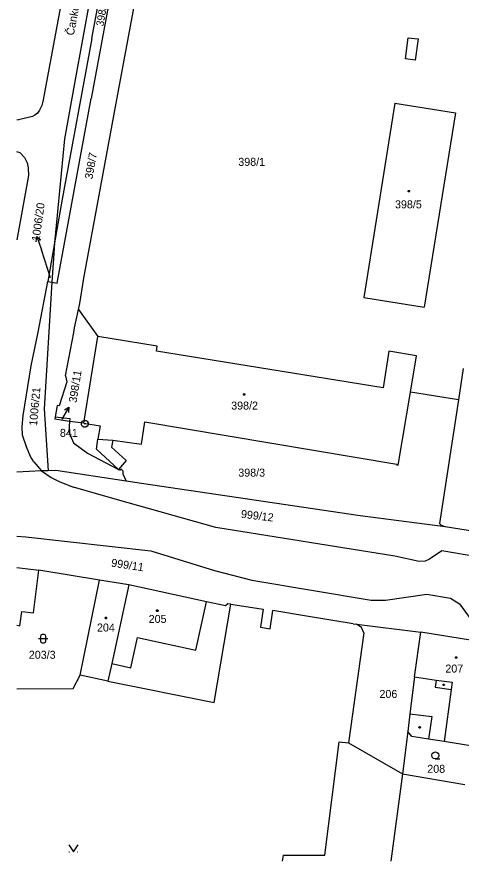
# Model space of a CAD drawing. Extents: x -851495 to -851222, y -1010479 to -1010202.
# Drawn here: x -851494.8 to -851400.4, y -1010478.7 to -1010299.4 of the extents above; entities that cross this region are included whole.
import ezdxf

# ---------------------------------------------------------------- set-up
doc = ezdxf.new("R2010")
doc.units = 0
for name, color, linetype in [('1', 7, 'Continuous'), ('12', 7, 'Continuous'), ('2', 7, 'Continuous'), ('3', 7, 'Continuous'), ('4', 7, 'Continuous'), ('5', 7, 'Continuous'), ('7', 7, 'Continuous'), ('8', 7, 'Continuous')]:
    doc.layers.add(name, color=color, linetype=linetype)

# ---------------------------------------------------------------- blocks, each defined once
blk = doc.blocks.new('101')
blk.add_line((-0.05, 0), (0.05, 0))
blk.add_lwpolyline([(0.19, 0.72), (0.53, 0.53), (0.72, 0.19), (0.72, -0.2), (0.53, -0.54), (0.19, -0.73), (-0.2, -0.73), (-0.54, -0.54), (-0.73, -0.2), (-0.73, 0.19), (-0.54, 0.53), (-0.2, 0.72), (0.19, 0.72)])
blk = doc.blocks.new('304')
blk.add_lwpolyline([(0, 0), (-0.38, 0.1), (-0.65, 0.37), (-0.75, 0.74), (-0.65, 1.11), (-0.38, 1.38), (-0.01, 1.48), (0.36, 1.38), (0.63, 1.11), (0.73, 0.73), (0.63, 0.35), (0.36, 0.08), (-0.02, -0.02), (0.98, -0.02)])
blk = doc.blocks.new('314')
for p, q in [((-0.95, 0), (-0.85, 0)), ((0.85, 0), (0.95, 0))]:
    blk.add_line(p, q)
blk.add_lwpolyline([(-1, 1.5), (0, 0), (1, 1.5)])
blk = doc.blocks.new('316')
for points in [[(-0.5, 1.5), (-0.4, 1.79), (-0.15, 1.97), (0.16, 1.97), (0.41, 1.79), (0.51, 1.5), (0.51, 0.5), (0.41, 0.21), (0.16, 0.03), (-0.15, 0.03), (-0.4, 0.21), (-0.5, 0.5), (-0.5, 1.5)], [(-1, 1), (0.27, 1), (1, 1)]]:
    blk.add_lwpolyline(points)
blk = doc.blocks.new('10292')
blk.add_line((0, 3), (0, 0))
blk.add_lwpolyline([(-0.5, 2), (0, 3), (0.5, 2)])
blk = doc.blocks.new('402')
blk.add_lwpolyline([(0.09, 0.15), (0.18, 0), (0.09, -0.15), (-0.09, -0.15), (-0.18, 0), (-0.09, 0.15), (0.09, 0.15)])
blk = doc.blocks.new('404')
blk.add_lwpolyline([(0, 0.17), (0.1, 0.15), (0.15, 0.06), (0.17, 0), (0.15, -0.09), (0.07, -0.16), (0, -0.17), (-0.09, -0.14), (-0.15, -0.08), (-0.17, 0), (-0.15, 0.09), (-0.07, 0.16), (0, 0.17)])

msp = doc.modelspace()

# ---------------------------------------------------------------- linework, layer by layer
at = {"layer": '1'}
for p, q in [((-851476.12, -1010278.09), (-851482.49, -1010313.06)), ((-851472.11, -1010279.3), (-851479.01, -1010316.73)), ((-851478.85, -1010303.92), (-851474.1, -1010278.46)), ((-851473.7, -1010317.66), (-851466.71, -1010279.81)), ((-851478.85, -1010303.92), (-851485.17, -1010338.09)), ((-851482.49, -1010313.06), (-851484.69, -1010325.27)), ((-851486.26, -1010355.89), (-851479.01, -1010316.73)), ((-851480.57, -1010354.84), (-851473.7, -1010317.66)), ((-851414.5, -1010317.69), (-851421.05, -1010358.97)), ((-851414.5, -1010317.69), (-851401.62, -1010319.76)), ((-851401.62, -1010319.76), (-851408.24, -1010361.02)), ((-851484.69, -1010325.27), (-851486.78, -1010347.37)), ((-851485.17, -1010338.09), (-851486.78, -1010347.37)), ((-851486.78, -1010347.37), (-851488.2, -1010355.55)), ((-851486.78, -1010347.37), (-851486.99, -1010349.59)), ((-851486.99, -1010349.59), (-851487.37, -1010355.7)), ((-851481.45, -1010360.24), (-851480.57, -1010354.84)), ((-851490.26, -1010366.32), (-851488.2, -1010355.55)), ((-851487.37, -1010355.7), (-851489.04, -1010382.57)), ((-851488.2, -1010355.55), (-851487.37, -1010355.7)), ((-851487.37, -1010355.7), (-851486.26, -1010355.89)), ((-851481.71, -1010361.49), (-851481.45, -1010360.24)), ((-851421.05, -1010358.97), (-851408.24, -1010361.02)), ((-851482.53, -1010365.43), (-851481.71, -1010361.49)), ((-851481.71, -1010361.49), (-851477.61, -1010367.22)), ((-851482.71, -1010366.38), (-851482.53, -1010365.43)), ((-851491.75, -1010373.45), (-851490.26, -1010366.32)), ((-851484.5, -1010375.57), (-851482.71, -1010366.38)), ((-851480.57, -1010385.67), (-851477.61, -1010367.22)), ((-851464.98, -1010369.26), (-851477.61, -1010367.22)), ((-851465.15, -1010370.35), (-851464.98, -1010369.26)), ((-851417.01, -1010378.12), (-851465.15, -1010370.35)), ((-851415.76, -1010370.37), (-851417.01, -1010378.12)), ((-851409.91, -1010371.33), (-851415.76, -1010370.37)), ((-851411.16, -1010379.06), (-851409.91, -1010371.33)), ((-851493.5, -1010383.99), (-851491.75, -1010373.45)), ((-851399.98, -1010374.03), (-851401, -1010380.7)), ((-851484.5, -1010375.57), (-851484.17, -1010376.85)), ((-851484.17, -1010376.85), (-851485.79, -1010381.99)), ((-851413.76, -1010394.54), (-851411.16, -1010379.06)), ((-851401, -1010380.7), (-851411.16, -1010379.06)), ((-851486.27, -1010381.9), (-851486.66, -1010384.3)), ((-851485.79, -1010381.99), (-851486.27, -1010381.9)), ((-851401, -1010380.7), (-851405.04, -1010406.96)), ((-851489.04, -1010382.57), (-851488.17, -1010395.75)), ((-851493.7, -1010386.4), (-851493.5, -1010383.99)), ((-851486.66, -1010384.3), (-851486.77, -1010384.83)), ((-851483.62, -1010385.26), (-851486.77, -1010384.83)), ((-851486.66, -1010384.3), (-851483.57, -1010384.66)), ((-851483.62, -1010385.26), (-851483.8, -1010387.52)), ((-851483.57, -1010384.66), (-851483.62, -1010385.26)), ((-851480.57, -1010385.67), (-851477.13, -1010386.23)), ((-851468.32, -1010390.14), (-851467.64, -1010385.34)), ((-851467.64, -1010385.34), (-851414.1, -1010394.33)), ((-851493.63, -1010388.21), (-851493.7, -1010386.4)), ((-851477.13, -1010386.23), (-851477.59, -1010389.03)), ((-851492.79, -1010390.64), (-851493.63, -1010388.21)), ((-851483.8, -1010387.52), (-851482.79, -1010389.85)), ((-851477.59, -1010389.03), (-851474.42, -1010389.28)), ((-851474.42, -1010389.28), (-851468.32, -1010390.14)), ((-851491.92, -1010392.7), (-851492.79, -1010390.64)), ((-851482.79, -1010389.85), (-851479.83, -1010392.05)), ((-851491.22, -1010393.86), (-851491.92, -1010392.7)), ((-851479.83, -1010392.05), (-851473.25, -1010395.45)), ((-851491.22, -1010393.86), (-851489.57, -1010395.79)), ((-851414.1, -1010394.33), (-851414.12, -1010394.47)), ((-851414.12, -1010394.47), (-851413.76, -1010394.54)), ((-851489.57, -1010395.79), (-851494.81, -1010396.04)), ((-851488.17, -1010395.75), (-851489.57, -1010395.79)), ((-851489.57, -1010395.79), (-851487.55, -1010397.2)), ((-851486.54, -1010395.71), (-851488.17, -1010395.75)), ((-851471.58, -1010397.95), (-851486.54, -1010395.71)), ((-851473.25, -1010395.45), (-851472.89, -1010395.62)), ((-851472.89, -1010395.62), (-851472.7, -1010395.33)), ((-851472.7, -1010395.33), (-851472.29, -1010395.78)), ((-851472.29, -1010395.78), (-851472.31, -1010396.38)), ((-851472.31, -1010396.38), (-851471.58, -1010397.95)), ((-851487.55, -1010397.2), (-851485.7, -1010398.11)), ((-851485.7, -1010398.11), (-851482.81, -1010399.27)), ((-851468.36, -1010398.49), (-851471.58, -1010397.95)), ((-851473.45, -1010401.92), (-851482.81, -1010399.27)), ((-851421.88, -1010405.32), (-851468.36, -1010398.49)), ((-851452.54, -1010407.81), (-851473.45, -1010401.92)), ((-851403.77, -1010407.65), (-851421.88, -1010405.32)), ((-851404.6, -1010407.41), (-851405.04, -1010406.96)), ((-851414.48, -1010413.88), (-851452.54, -1010407.81)), ((-851403.77, -1010407.65), (-851404.6, -1010407.41)), ((-851369.92, -1010413.18), (-851403.77, -1010407.65)), ((-851494.81, -1010409.61), (-851492.93, -1010409.8)), ((-851492.93, -1010409.8), (-851466.33, -1010412.75)), ((-851466.33, -1010412.75), (-851452.79, -1010416.91)), ((-851409.35, -1010415.03), (-851414.48, -1010413.88)), ((-851404.51, -1010412.78), (-851407.12, -1010414.56)), ((-851389.99, -1010415.2), (-851404.51, -1010412.78)), ((-851408.08, -1010414.98), (-851409.35, -1010415.03)), ((-851407.12, -1010414.56), (-851408.08, -1010414.98)), ((-851494.81, -1010416.3), (-851490.12, -1010416.88)), ((-851491.27, -1010425.94), (-851490.12, -1010416.88)), ((-851477.24, -1010418.97), (-851490.12, -1010416.88)), ((-851452.79, -1010416.91), (-851444.86, -1010418.99)), ((-851481.35, -1010439.14), (-851477.24, -1010418.97)), ((-851470.99, -1010419.98), (-851477.24, -1010418.97)), ((-851444.86, -1010418.99), (-851419.5, -1010423.21)), ((-851470.99, -1010419.98), (-851474.66, -1010436.68)), ((-851454.51, -1010423.6), (-851470.99, -1010419.98)), ((-851419.5, -1010423.21), (-851416.51, -1010423.25)), ((-851416.51, -1010423.25), (-851407.68, -1010421.95)), ((-851407.68, -1010421.95), (-851402.7, -1010422.8)), ((-851402.7, -1010422.8), (-851400.73, -1010423.98)), ((-851450.49, -1010424.44), (-851454.51, -1010423.6)), ((-851452.87, -1010444.98), (-851449.33, -1010424.05)), ((-851450.01, -1010424.02), (-851450.49, -1010424.44)), ((-851449.33, -1010424.05), (-851450.01, -1010424.02)), ((-851449.33, -1010424.05), (-851442.46, -1010425.14)), ((-851442.46, -1010425.14), (-851443.06, -1010428.96)), ((-851400.73, -1010423.98), (-851397.15, -1010428.97)), ((-851494.17, -1010428.65), (-851493.78, -1010425.62)), ((-851493.78, -1010425.62), (-851491.27, -1010425.94)), ((-851441, -1010429.3), (-851440.4, -1010425.46)), ((-851433.27, -1010426.65), (-851440.4, -1010425.46)), ((-851423.33, -1010428.29), (-851433.27, -1010426.65)), ((-851494.81, -1010428.57), (-851494.17, -1010428.65)), ((-851423.33, -1010428.29), (-851422.63, -1010428.32)), ((-851422.63, -1010428.32), (-851408.97, -1010430.02)), ((-851421.57, -1010429.04), (-851422.63, -1010428.32)), ((-851443.06, -1010428.96), (-851441, -1010429.3)), ((-851421.11, -1010430.17), (-851424.34, -1010453.54)), ((-851421.11, -1010430.17), (-851421.57, -1010429.04)), ((-851410.32, -1010439.54), (-851408.97, -1010430.02)), ((-851395.3, -1010432.22), (-851408.97, -1010430.02)), ((-851474.66, -1010436.68), (-851475.48, -1010440.43)), ((-851482.86, -1010442.01), (-851481.35, -1010439.14)), ((-851475.48, -1010440.43), (-851481.35, -1010439.14)), ((-851475.48, -1010440.43), (-851452.87, -1010444.98)), ((-851410.32, -1010439.54), (-851411.29, -1010447.38)), ((-851494.81, -1010442.09), (-851482.86, -1010442.01)), ((-851411.29, -1010447.38), (-851411.76, -1010451.15)), ((-851411.76, -1010451.15), (-851412.88, -1010460.14)), ((-851410.91, -1010452.19), (-851411.76, -1010451.15)), ((-851429.34, -1010477.36), (-851426.33, -1010453.35)), ((-851426.33, -1010453.35), (-851424.34, -1010453.54)), ((-851424.34, -1010453.54), (-851412.88, -1010460.14)), ((-851407.36, -1010452.74), (-851410.91, -1010452.19)), ((-851404.03, -1010453.26), (-851407.36, -1010452.74)), ((-851398.42, -1010454.14), (-851404.03, -1010453.26)), ((-851412.88, -1010460.14), (-851415.35, -1010478.65)), ((-851412.88, -1010460.14), (-851399.59, -1010462.37)), ((-851438.34, -1010478.65), (-851438.17, -1010477.36)), ((-851438.17, -1010477.36), (-851429.34, -1010477.36))]:
    msp.add_line(p, q, dxfattribs=at)
at = {"layer": '12'}
for p, q in [((-851414.5, -1010317.69), (-851421.05, -1010358.97)), ((-851414.5, -1010317.69), (-851401.62, -1010319.76)), ((-851401.62, -1010319.76), (-851408.24, -1010361.02)), ((-851421.05, -1010358.97), (-851408.24, -1010361.02)), ((-851480.57, -1010385.67), (-851477.61, -1010367.22)), ((-851464.98, -1010369.26), (-851477.61, -1010367.22)), ((-851465.15, -1010370.35), (-851464.98, -1010369.26)), ((-851417.01, -1010378.12), (-851465.15, -1010370.35)), ((-851415.76, -1010370.37), (-851417.01, -1010378.12)), ((-851409.91, -1010371.33), (-851415.76, -1010370.37)), ((-851411.16, -1010379.06), (-851409.91, -1010371.33)), ((-851413.76, -1010394.54), (-851411.16, -1010379.06)), ((-851480.57, -1010385.67), (-851477.13, -1010386.23)), ((-851468.32, -1010390.14), (-851467.64, -1010385.34)), ((-851467.64, -1010385.34), (-851414.1, -1010394.33)), ((-851477.13, -1010386.23), (-851477.59, -1010389.03)), ((-851477.59, -1010389.03), (-851474.42, -1010389.28)), ((-851474.42, -1010389.28), (-851468.32, -1010390.14)), ((-851414.1, -1010394.33), (-851414.12, -1010394.47)), ((-851414.12, -1010394.47), (-851413.76, -1010394.54)), ((-851494.81, -1010416.3), (-851490.12, -1010416.88)), ((-851491.27, -1010425.94), (-851490.12, -1010416.88)), ((-851481.35, -1010439.14), (-851477.24, -1010418.97)), ((-851470.99, -1010419.98), (-851477.24, -1010418.97)), ((-851470.99, -1010419.98), (-851474.66, -1010436.68)), ((-851470.99, -1010419.98), (-851474.66, -1010436.68)), ((-851454.51, -1010423.6), (-851470.99, -1010419.98)), ((-851456.76, -1010433.86), (-851454.51, -1010423.6)), ((-851494.17, -1010428.65), (-851493.78, -1010425.62)), ((-851493.78, -1010425.62), (-851491.27, -1010425.94)), ((-851494.81, -1010428.57), (-851494.17, -1010428.65)), ((-851410.32, -1010439.54), (-851408.97, -1010430.02)), ((-851395.3, -1010432.22), (-851408.97, -1010430.02)), ((-851470.58, -1010437.58), (-851469.16, -1010431.13)), ((-851469.16, -1010431.13), (-851456.76, -1010433.86)), ((-851474.66, -1010436.68), (-851475.48, -1010440.43)), ((-851474.66, -1010436.68), (-851470.58, -1010437.58)), ((-851475.48, -1010440.43), (-851481.35, -1010439.14)), ((-851410.32, -1010439.54), (-851405.72, -1010440.2)), ((-851405.72, -1010440.2), (-851402.29, -1010440.68)), ((-851402.29, -1010440.68), (-851402.5, -1010442.17)), ((-851402.5, -1010442.17), (-851404.03, -1010453.26)), ((-851398.42, -1010454.14), (-851404.03, -1010453.26))]:
    msp.add_line(p, q, dxfattribs=at)
at = {"layer": '4'}
for p, q in [((-851483.26, -1010284.78), (-851489.25, -1010316.96)), ((-851412.26, -1010308.27), (-851411.68, -1010303.78)), ((-851411.68, -1010303.78), (-851409.54, -1010304.05)), ((-851409.54, -1010304.05), (-851410.16, -1010308.56)), ((-851410.16, -1010308.56), (-851412.26, -1010308.27)), ((-851489.25, -1010316.96), (-851489.54, -1010318.17)), ((-851490.02, -1010319.21), (-851490.43, -1010319.79)), ((-851489.54, -1010318.17), (-851490.02, -1010319.21)), ((-851494.81, -1010321.16), (-851494.46, -1010321.21)), ((-851491.47, -1010320.53), (-851494.46, -1010321.21)), ((-851490.96, -1010320.24), (-851491.47, -1010320.53)), ((-851490.43, -1010319.79), (-851490.96, -1010320.24)), ((-851494.14, -1010328.22), (-851494.81, -1010327.99)), ((-851493.19, -1010329.25), (-851494.14, -1010328.22)), ((-851493.19, -1010329.25), (-851492.64, -1010330.34)), ((-851492.64, -1010330.34), (-851492.43, -1010331.4)), ((-851492.43, -1010331.4), (-851492.35, -1010333.02)), ((-851492.35, -1010333.02), (-851494.81, -1010346.68)), ((-851480.57, -1010385.67), (-851483.62, -1010385.26)), ((-851477.92, -1010391.17), (-851477.59, -1010389.03)), ((-851474.42, -1010389.28), (-851474.68, -1010390.74)), ((-851474.68, -1010390.74), (-851471.62, -1010393.58)), ((-851473.25, -1010395.45), (-851477.92, -1010391.17)), ((-851471.62, -1010393.58), (-851473.25, -1010395.45)), ((-851456.76, -1010433.86), (-851454.51, -1010423.6)), ((-851470.58, -1010437.58), (-851469.16, -1010431.13)), ((-851469.16, -1010431.13), (-851456.76, -1010433.86)), ((-851474.66, -1010436.68), (-851470.58, -1010437.58)), ((-851410.32, -1010439.54), (-851405.72, -1010440.2)), ((-851405.72, -1010440.2), (-851405.93, -1010441.68)), ((-851405.72, -1010440.2), (-851402.29, -1010440.68)), ((-851402.29, -1010440.68), (-851402.5, -1010442.17)), ((-851405.93, -1010441.68), (-851402.5, -1010442.17)), ((-851402.5, -1010442.17), (-851404.03, -1010453.26)), ((-851411.29, -1010447.38), (-851406.62, -1010447.96)), ((-851406.62, -1010447.96), (-851407.36, -1010452.74))]:
    msp.add_line(p, q, dxfattribs=at)
at = {"layer": '7'}
msp.add_line((-851487.69, -1010354.77), (-851489.61, -1010348.85), dxfattribs=at)

# ---------------------------------------------------------------- block references
at = {"layer": '3'}
for name, p in [('316', (-851489.23, -1010432.4)), ('304', (-851405.88, -1010456.93)), ('314', (-851482.8, -1010476.67))]:
    msp.add_blockref(name, p, dxfattribs=at)
at = {"layer": '5'}
for name, p in [('404', (-851411.5, -1010336.38)), ('404', (-851446.5, -1010379.55)), ('404', (-851475.92, -1010427.01)), ('404', (-851464.97, -1010425.47)), ('404', (-851401.46, -1010435.42)), ('402', (-851404.13, -1010441.24)), ('402', (-851409.22, -1010450.24))]:
    msp.add_blockref(name, p, dxfattribs=at)
at = {"layer": '7'}
for p, rotation in [((-851489.61, -1010348.85), 17.933579), ((-851485.28, -1010384.81), -30.83574700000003)]:
    msp.add_blockref('10292', p, dxfattribs=dict(at, rotation=rotation))
at = {"layer": '8'}
msp.add_blockref('101', (-851480.38, -1010385.77), dxfattribs=at)

# ---------------------------------------------------------------- texts
at = {"layer": '2'}
for s, height, rotation, p in [('398/8', 1.6, 80.501, (-851476.42, -1010301.45)), ('398/7', 1.7, 80.042, (-851478.75, -1010333.94)), ('1006/21', 1.7, 84.74, (-851490.54, -1010386.27)), ('999/12', 1.7, 353.228, (-851447.27, -1010405.73)), ('999/11', 1.7, 351.567, (-851474.85, -1010416.09))]:
    msp.add_text(s, height=height, rotation=rotation, dxfattribs=at).set_placement(p)
for s, height, p in [('398/1', 1.7, (-851447.76, -1010331)), ('398/5', 1.7, (-851414.46, -1010340.02)), ('1006/20', 0.1, (-851488.04, -1010354.77)), ('398/2', 1.7, (-851449.27, -1010382.76)), ('398/11', 0.1, (-851485.27, -1010384.81)), ('398/3', 1.7, (-851447.76, -1010397)), ('205', 1.7, (-851466.8, -1010428.07)), ('204', 1.7, (-851477.79, -1010429.89)), ('203/3', 1.7, (-851492.27, -1010435.68)), ('207', 1.7, (-851403.76, -1010438.61)), ('206', 1.7, (-851417.76, -1010444)), ('208', 1.7, (-851407.6, -1010459.9))]:
    msp.add_text(s, height=height, dxfattribs=at).set_placement(p)
at = {"layer": '7'}
for s, rotation, p in [('Čankovská', 79.297, (-851482.73, -1010303.41)), ('1006/20', 82.162, (-851490, -1010347.11)), ('398/11', 81.016, (-851482.13, -1010381.4))]:
    msp.add_text(s, height=1.7, rotation=rotation, dxfattribs=at).set_placement(p)
at = {"layer": '8'}
msp.add_text('841', height=1.7, dxfattribs=at).set_placement((-851485.66, -1010388.56))

doc.saveas('drawing.dxf')
